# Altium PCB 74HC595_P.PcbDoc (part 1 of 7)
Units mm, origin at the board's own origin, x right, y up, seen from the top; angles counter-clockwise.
Board outline 89.11 x 89.03 mm, 2 copper layers (Top Layer, Bottom Layer); 552 components, 23 nets, 1488 pads, 408 vias.
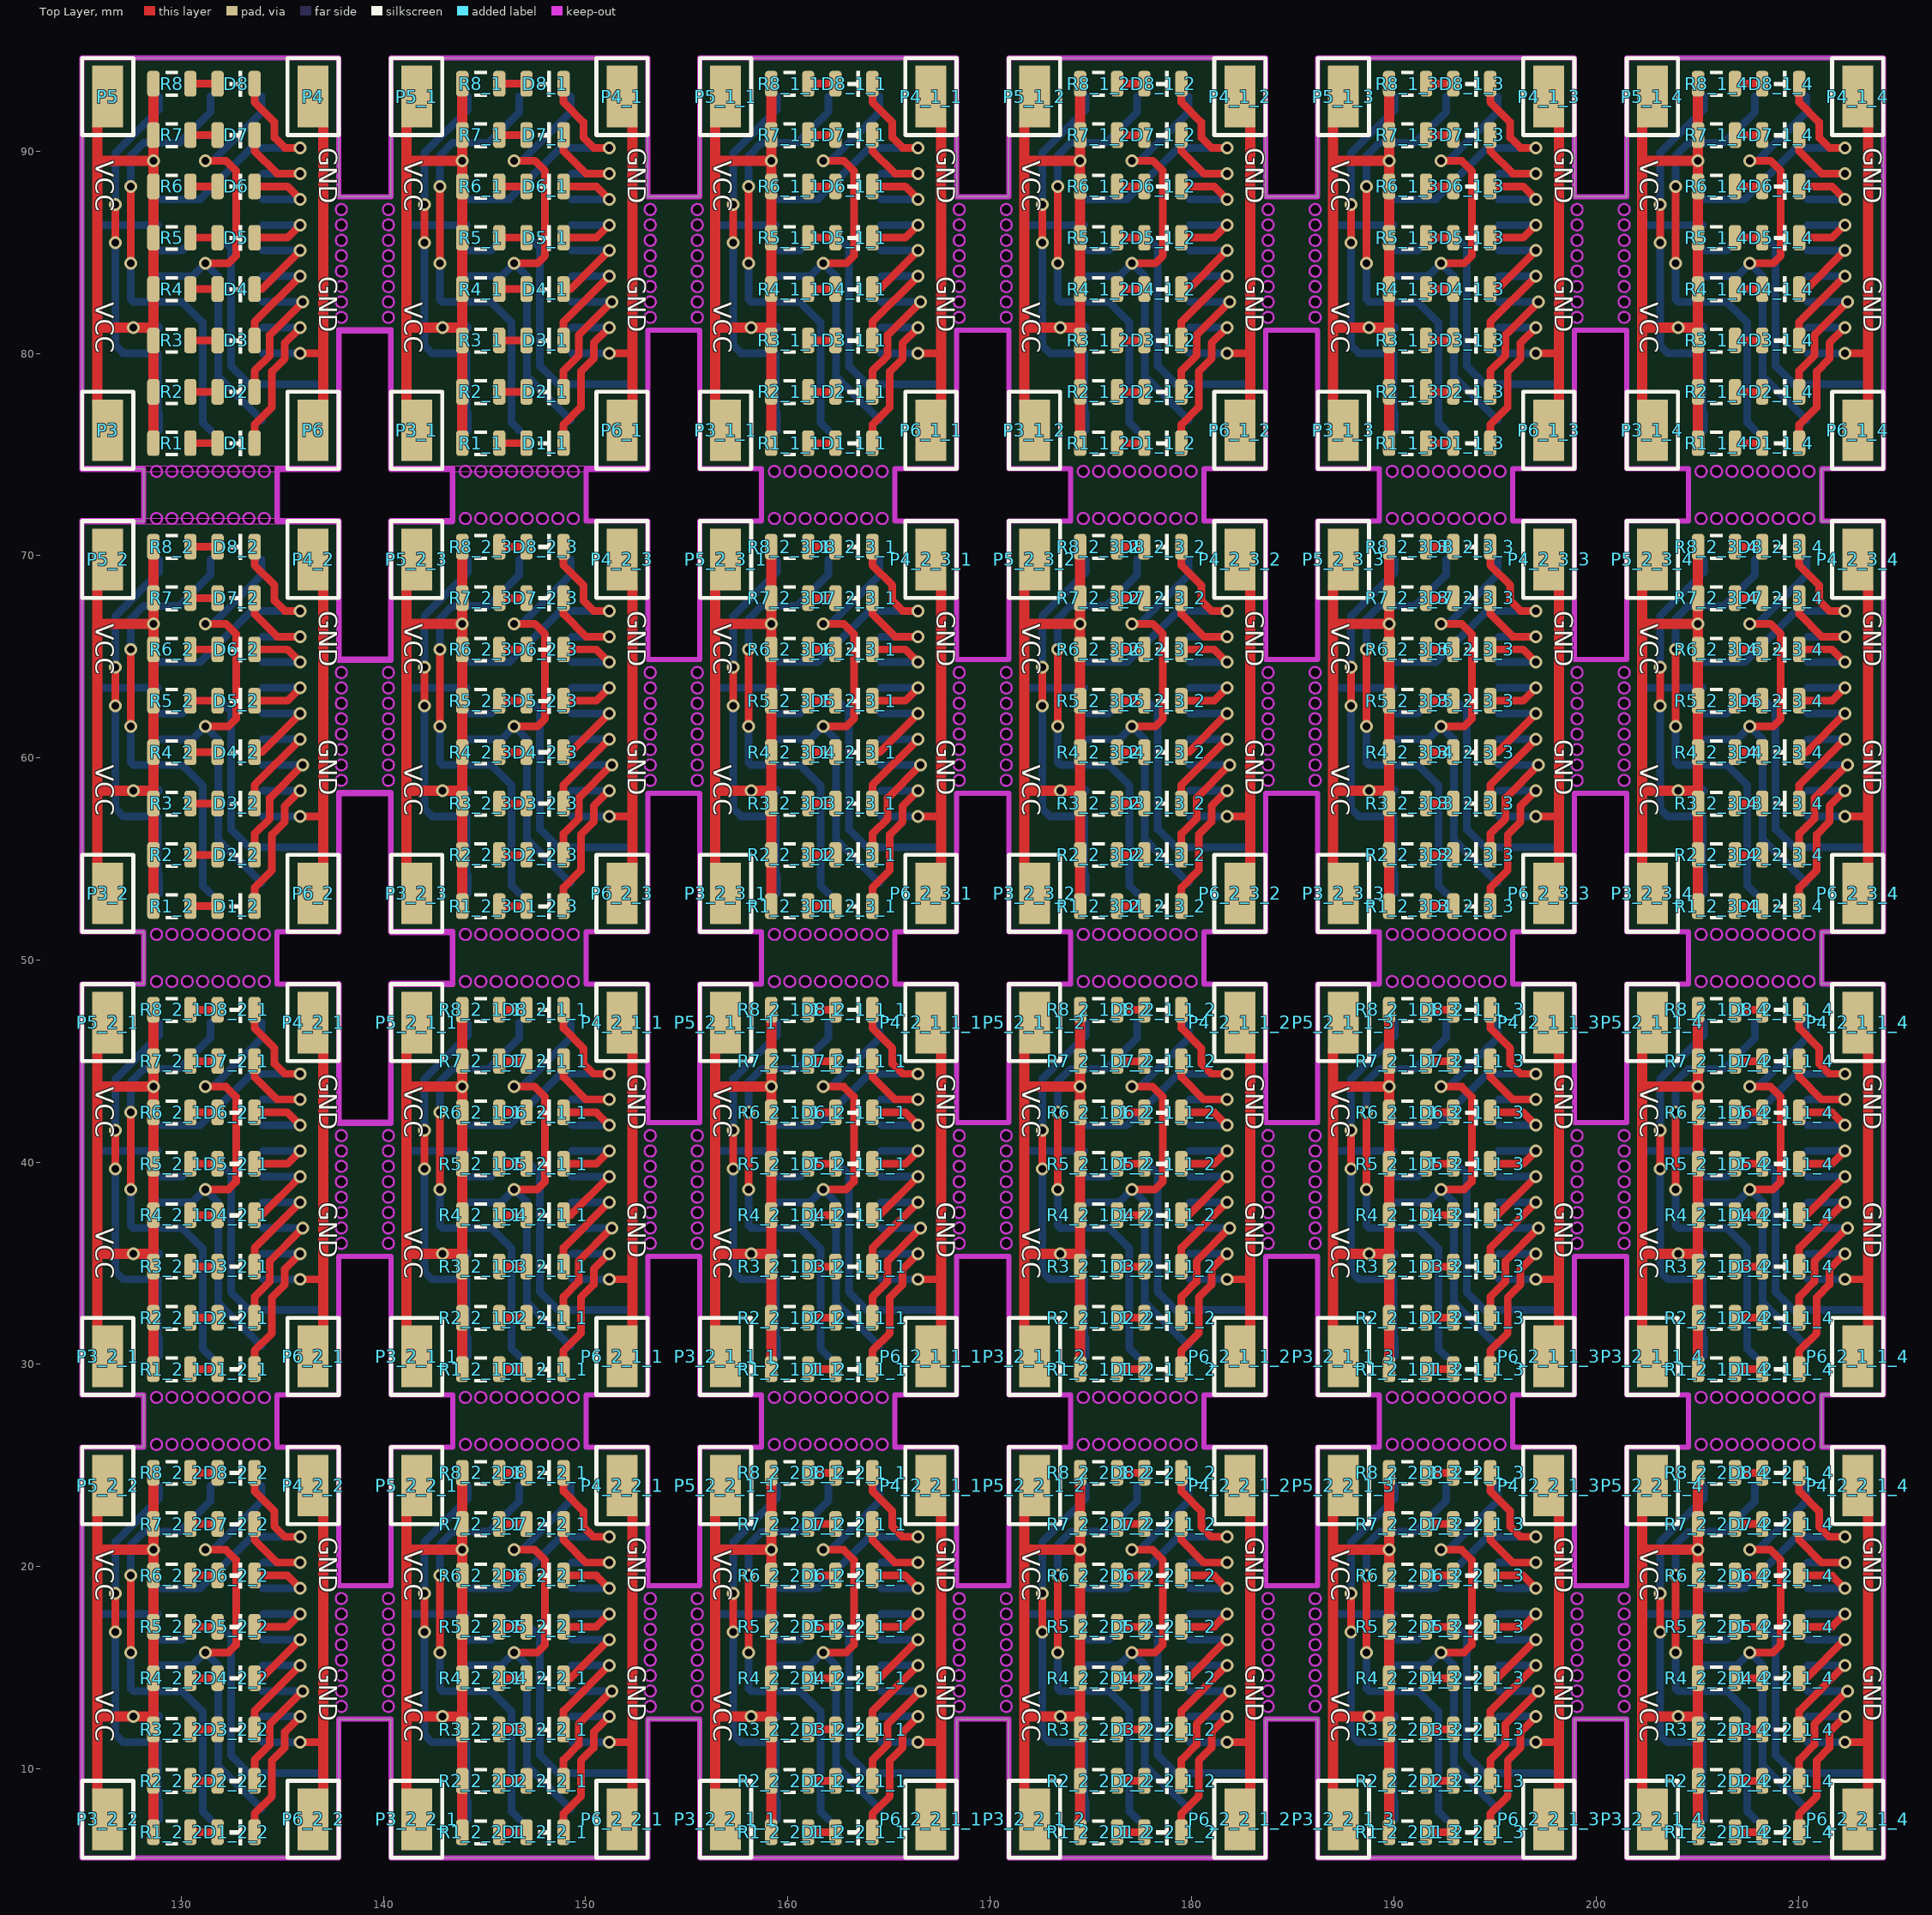
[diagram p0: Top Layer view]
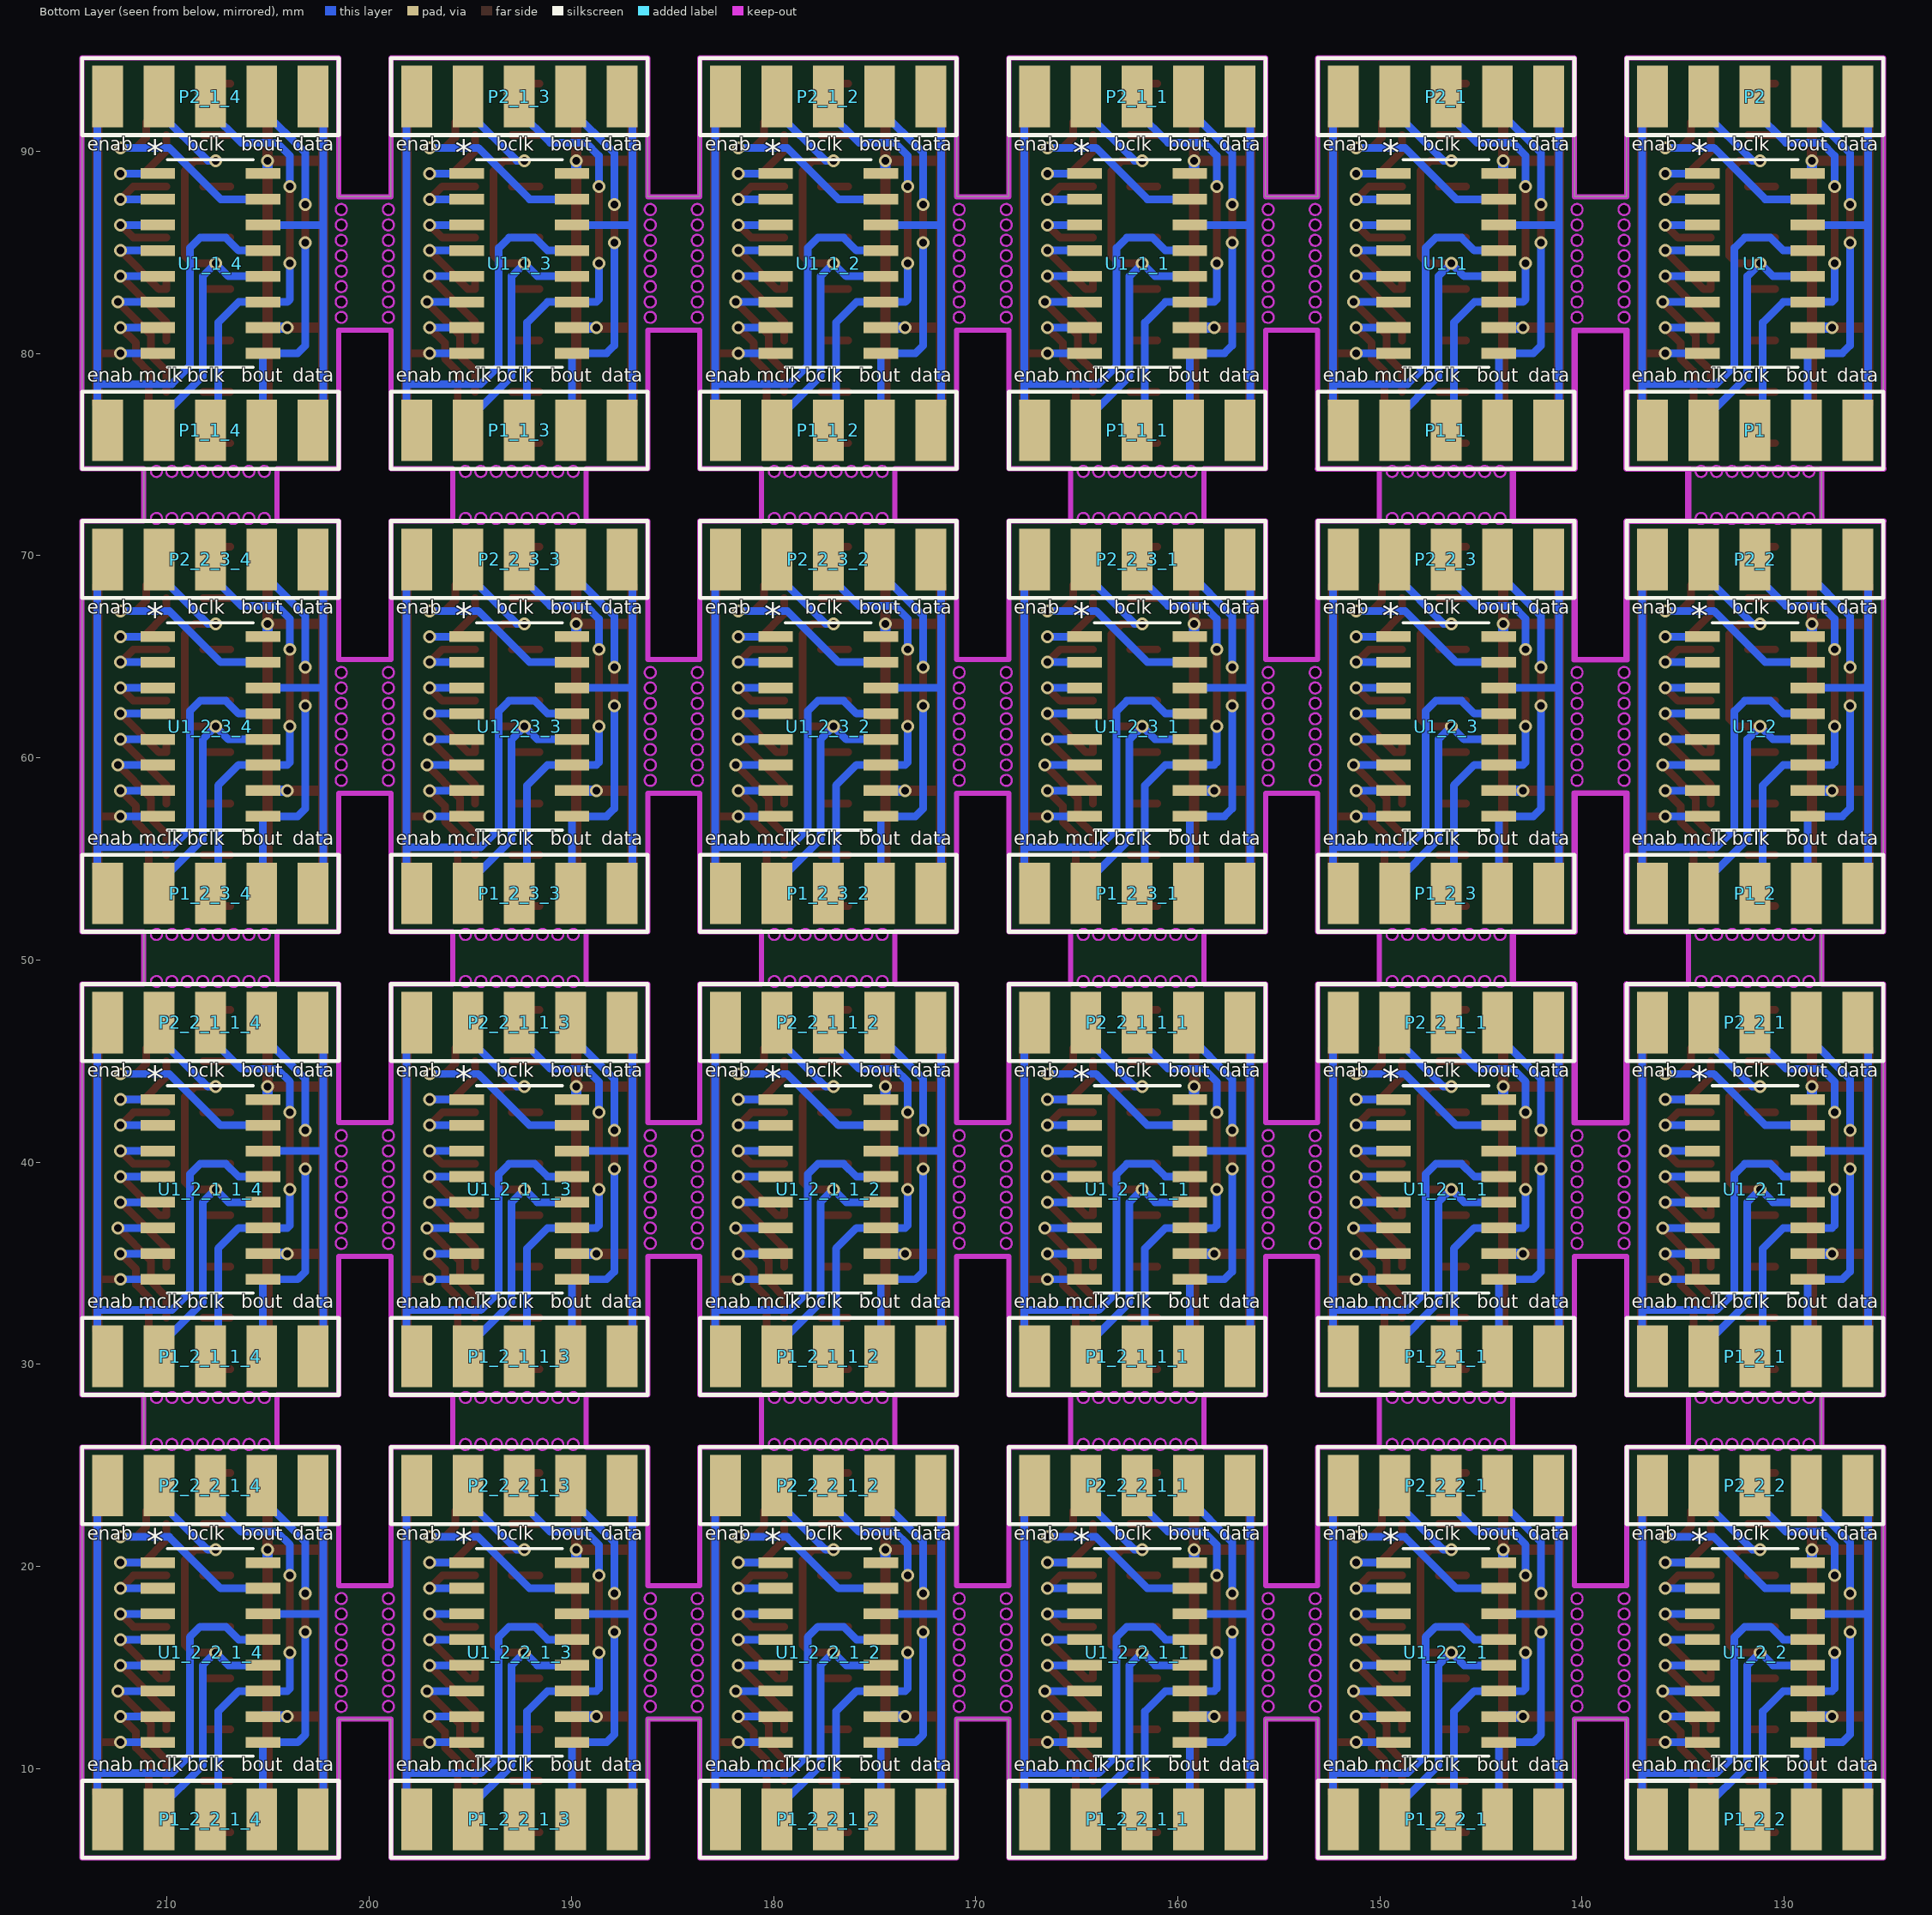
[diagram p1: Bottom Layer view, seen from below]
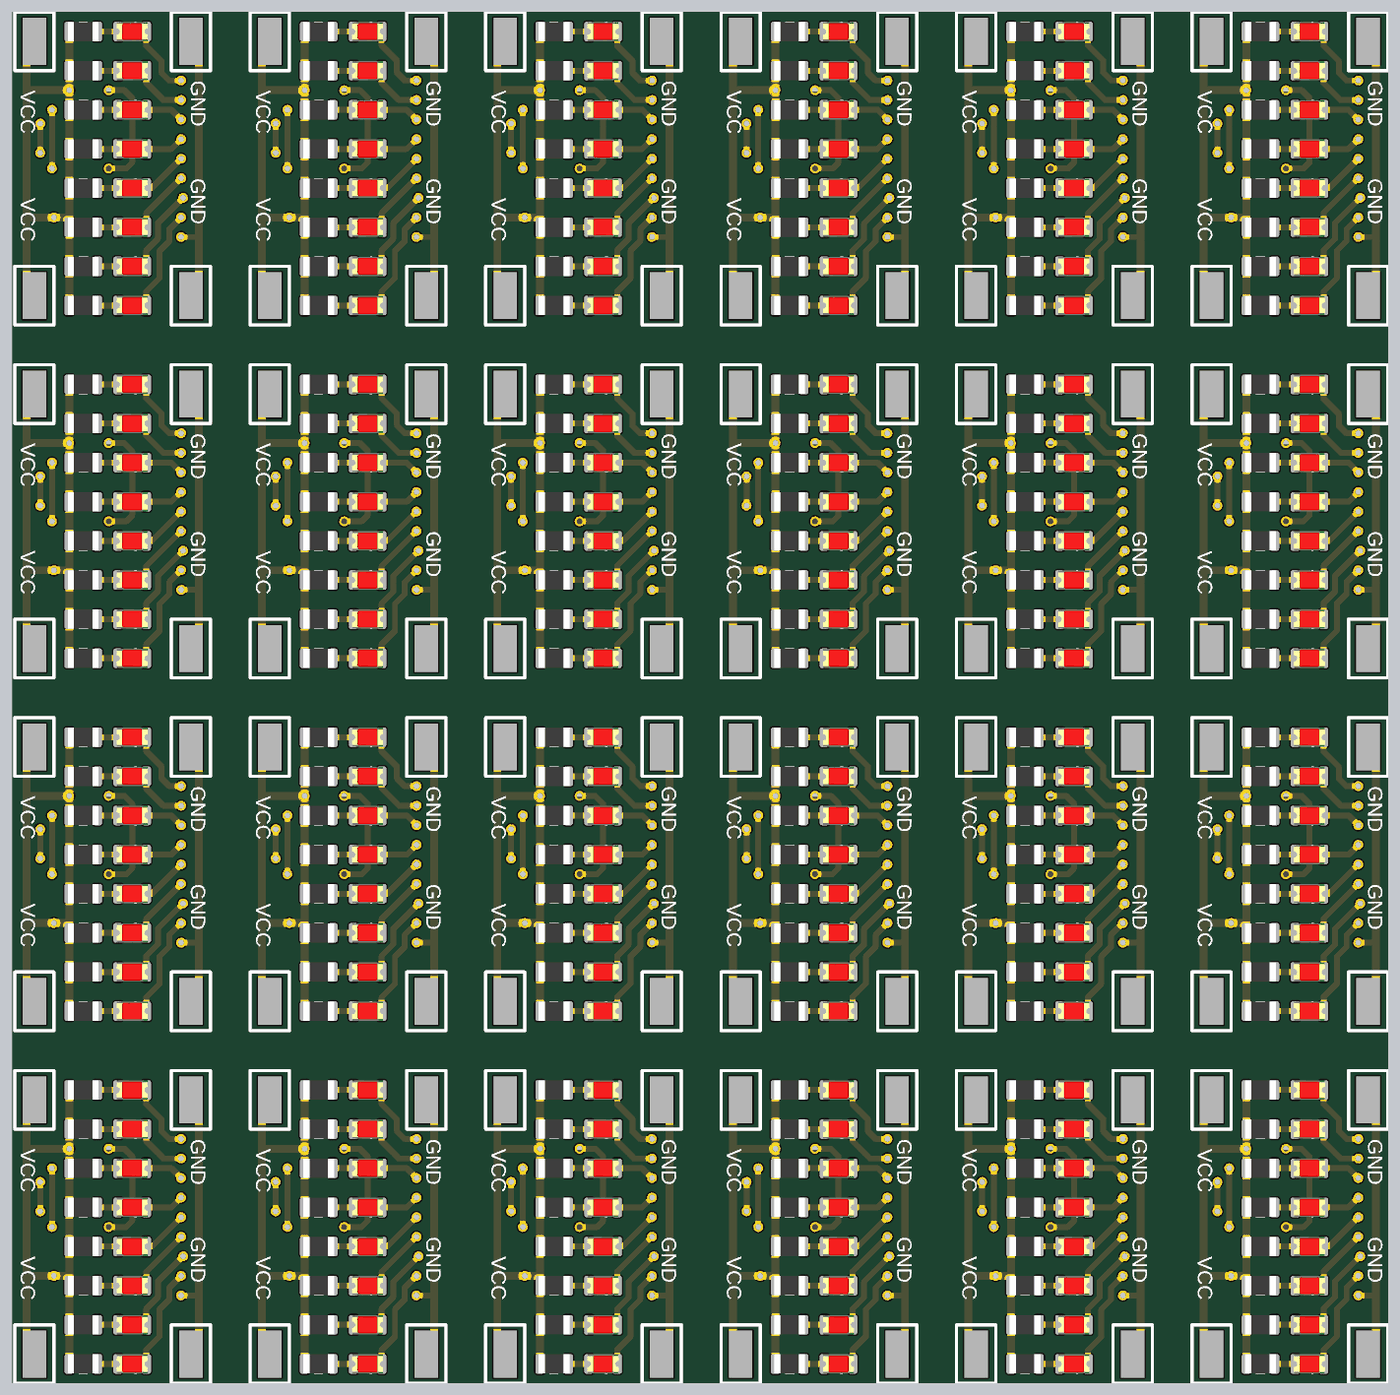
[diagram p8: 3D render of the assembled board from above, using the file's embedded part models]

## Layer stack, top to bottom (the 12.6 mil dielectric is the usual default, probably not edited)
Top Solder: solder mask 0.0102, Solder Resist, Dk 3.5
Top Layer: signal copper 0.0356
Dielectric 1: dielectric 0.32, FR-4, Dk 4.8
Bottom Layer: signal copper 0.0356
Bottom Solder: solder mask 0.0102, Solder Resist, Dk 3.5

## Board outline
125.095,25.909 128.143,25.909 128.143,28.491 125.095,28.491 125.095,48.811 128.143,48.811 128.143,51.393 125.095,51.393 125.095,71.713 128.143,71.713 128.143,74.295 125.095,74.295 125.095,94.615 137.795,94.615 137.795,87.757 140.377,87.757 140.377,94.615 153.077,94.615 153.077,87.757 155.659,87.757 155.659,94.615 168.359,94.615 168.359,87.757 170.941,87.757 170.941,94.615 183.641,94.615 183.641,87.757 186.223,87.757 186.223,94.615 198.923,94.615 198.923,87.757 201.505,87.757 201.505,94.615 214.205,94.615 214.205,74.295 211.157,74.295 211.157,71.713 214.205,71.713 214.205,51.393 211.157,51.393 211.157,48.811 214.205,48.811 214.205,28.491 211.157,28.491 211.157,25.909 214.205,25.909 214.205,5.589 201.505,5.589 201.505,12.447 198.923,12.447 198.923,5.589 186.223,5.589 186.223,12.447 183.641,12.447 183.641,5.589 170.941,5.589 170.941,12.447 168.359,12.447 168.359,5.589 155.659,5.589 155.659,12.447 153.077,12.447 153.077,5.589 140.377,5.589 140.377,12.447 137.795,12.447 137.795,5.589 125.095,5.589
cut-out: 205.188,25.761 ccw(c205.188,26.036) 205.463,26.036 ccw(c205.188,26.036) 205.188,26.311 ccw(c205.188,26.036) 204.913,26.036 ccw(c205.188,26.036)
cut-out: 205.188,28.089 ccw(c205.188,28.364) 205.463,28.364 ccw(c205.188,28.364) 205.188,28.639 ccw(c205.188,28.364) 204.913,28.364 ccw(c205.188,28.364)
cut-out: 205.95,25.761 ccw(c205.95,26.036) 206.225,26.036 ccw(c205.95,26.036) 205.95,26.311 ccw(c205.95,26.036) 205.675,26.036 ccw(c205.95,26.036)
cut-out: 206.712,28.089 cw(c206.712,28.364) 206.437,28.364 cw(c206.712,28.364) 206.712,28.639 cw(c206.712,28.364) 206.987,28.364 cw(c206.712,28.364)
cut-out: 205.95,28.089 ccw(c205.95,28.364) 206.225,28.364 ccw(c205.95,28.364) 205.95,28.639 ccw(c205.95,28.364) 205.675,28.364 ccw(c205.95,28.364)
cut-out: 207.474,28.089 ccw(c207.474,28.364) 207.749,28.364 ccw(c207.474,28.364) 207.474,28.639 ccw(c207.474,28.364) 207.199,28.364 ccw(c207.474,28.364)
cut-out: 207.474,25.761 ccw(c207.474,26.036) 207.749,26.036 ccw(c207.474,26.036) 207.474,26.311 ccw(c207.474,26.036) 207.199,26.036 ccw(c207.474,26.036)
cut-out: 206.712,25.761 ccw(c206.712,26.036) 206.987,26.036 ccw(c206.712,26.036) 206.712,26.311 ccw(c206.712,26.036) 206.437,26.036 ccw(c206.712,26.036)
cut-out: 208.236,25.761 ccw(c208.236,26.036) 208.511,26.036 ccw(c208.236,26.036) 208.236,26.311 ccw(c208.236,26.036) 207.961,26.036 ccw(c208.236,26.036)
cut-out: 208.998,25.761 ccw(c208.998,26.036) 209.273,26.036 ccw(c208.998,26.036) 208.998,26.311 ccw(c208.998,26.036) 208.723,26.036 ccw(c208.998,26.036)
cut-out: 209.76,25.761 ccw(c209.76,26.036) 210.035,26.036 ccw(c209.76,26.036) 209.76,26.311 ccw(c209.76,26.036) 209.485,26.036 ccw(c209.76,26.036)
cut-out: 210.522,25.761 ccw(c210.522,26.036) 210.797,26.036 ccw(c210.522,26.036) 210.522,26.311 ccw(c210.522,26.036) 210.247,26.036 ccw(c210.522,26.036)
cut-out: 210.522,28.089 ccw(c210.522,28.364) 210.797,28.364 ccw(c210.522,28.364) 210.522,28.639 ccw(c210.522,28.364) 210.247,28.364 ccw(c210.522,28.364)
cut-out: 209.76,28.089 ccw(c209.76,28.364) 210.035,28.364 ccw(c209.76,28.364) 209.76,28.639 ccw(c209.76,28.364) 209.485,28.364 ccw(c209.76,28.364)
cut-out: 208.998,28.089 ccw(c208.998,28.364) 209.273,28.364 ccw(c208.998,28.364) 208.998,28.639 ccw(c208.998,28.364) 208.723,28.364 ccw(c208.998,28.364)
cut-out: 208.236,28.089 ccw(c208.236,28.364) 208.511,28.364 ccw(c208.236,28.364) 208.236,28.639 ccw(c208.236,28.364) 207.961,28.364 ccw(c208.236,28.364)
cut-out: 189.906,25.761 ccw(c189.906,26.036) 190.181,26.036 ccw(c189.906,26.036) 189.906,26.311 ccw(c189.906,26.036) 189.631,26.036 ccw(c189.906,26.036)
cut-out: 189.906,28.089 ccw(c189.906,28.364) 190.181,28.364 ccw(c189.906,28.364) 189.906,28.639 ccw(c189.906,28.364) 189.631,28.364 ccw(c189.906,28.364)
cut-out: 190.668,25.761 ccw(c190.668,26.036) 190.943,26.036 ccw(c190.668,26.036) 190.668,26.311 ccw(c190.668,26.036) 190.393,26.036 ccw(c190.668,26.036)
cut-out: 191.43,28.089 cw(c191.43,28.364) 191.155,28.364 cw(c191.43,28.364) 191.43,28.639 cw(c191.43,28.364) 191.705,28.364 cw(c191.43,28.364)
cut-out: 190.668,28.089 ccw(c190.668,28.364) 190.943,28.364 ccw(c190.668,28.364) 190.668,28.639 ccw(c190.668,28.364) 190.393,28.364 ccw(c190.668,28.364)
cut-out: 192.192,28.089 ccw(c192.192,28.364) 192.467,28.364 ccw(c192.192,28.364) 192.192,28.639 ccw(c192.192,28.364) 191.917,28.364 ccw(c192.192,28.364)
cut-out: 192.192,25.761 ccw(c192.192,26.036) 192.467,26.036 ccw(c192.192,26.036) 192.192,26.311 ccw(c192.192,26.036) 191.917,26.036 ccw(c192.192,26.036)
cut-out: 191.43,25.761 ccw(c191.43,26.036) 191.705,26.036 ccw(c191.43,26.036) 191.43,26.311 ccw(c191.43,26.036) 191.155,26.036 ccw(c191.43,26.036)
cut-out: 192.954,25.761 ccw(c192.954,26.036) 193.229,26.036 ccw(c192.954,26.036) 192.954,26.311 ccw(c192.954,26.036) 192.679,26.036 ccw(c192.954,26.036)
cut-out: 193.716,25.761 ccw(c193.716,26.036) 193.991,26.036 ccw(c193.716,26.036) 193.716,26.311 ccw(c193.716,26.036) 193.441,26.036 ccw(c193.716,26.036)
cut-out: 194.478,25.761 ccw(c194.478,26.036) 194.753,26.036 ccw(c194.478,26.036) 194.478,26.311 ccw(c194.478,26.036) 194.203,26.036 ccw(c194.478,26.036)
cut-out: 195.24,25.761 ccw(c195.24,26.036) 195.515,26.036 ccw(c195.24,26.036) 195.24,26.311 ccw(c195.24,26.036) 194.965,26.036 ccw(c195.24,26.036)
cut-out: 195.24,28.089 ccw(c195.24,28.364) 195.515,28.364 ccw(c195.24,28.364) 195.24,28.639 ccw(c195.24,28.364) 194.965,28.364 ccw(c195.24,28.364)
cut-out: 194.478,28.089 ccw(c194.478,28.364) 194.753,28.364 ccw(c194.478,28.364) 194.478,28.639 ccw(c194.478,28.364) 194.203,28.364 ccw(c194.478,28.364)
cut-out: 193.716,28.089 ccw(c193.716,28.364) 193.991,28.364 ccw(c193.716,28.364) 193.716,28.639 ccw(c193.716,28.364) 193.441,28.364 ccw(c193.716,28.364)
cut-out: 192.954,28.089 ccw(c192.954,28.364) 193.229,28.364 ccw(c192.954,28.364) 192.954,28.639 ccw(c192.954,28.364) 192.679,28.364 ccw(c192.954,28.364)
cut-out: 174.624,25.761 ccw(c174.624,26.036) 174.899,26.036 ccw(c174.624,26.036) 174.624,26.311 ccw(c174.624,26.036) 174.349,26.036 ccw(c174.624,26.036)
cut-out: 174.624,28.089 ccw(c174.624,28.364) 174.899,28.364 ccw(c174.624,28.364) 174.624,28.639 ccw(c174.624,28.364) 174.349,28.364 ccw(c174.624,28.364)
cut-out: 175.386,25.761 ccw(c175.386,26.036) 175.661,26.036 ccw(c175.386,26.036) 175.386,26.311 ccw(c175.386,26.036) 175.111,26.036 ccw(c175.386,26.036)
cut-out: 176.148,28.089 cw(c176.148,28.364) 175.873,28.364 cw(c176.148,28.364) 176.148,28.639 cw(c176.148,28.364) 176.423,28.364 cw(c176.148,28.364)
cut-out: 175.386,28.089 ccw(c175.386,28.364) 175.661,28.364 ccw(c175.386,28.364) 175.386,28.639 ccw(c175.386,28.364) 175.111,28.364 ccw(c175.386,28.364)
cut-out: 176.91,28.089 ccw(c176.91,28.364) 177.185,28.364 ccw(c176.91,28.364) 176.91,28.639 ccw(c176.91,28.364) 176.635,28.364 ccw(c176.91,28.364)
cut-out: 176.91,25.761 ccw(c176.91,26.036) 177.185,26.036 ccw(c176.91,26.036) 176.91,26.311 ccw(c176.91,26.036) 176.635,26.036 ccw(c176.91,26.036)
cut-out: 176.148,25.761 ccw(c176.148,26.036) 176.423,26.036 ccw(c176.148,26.036) 176.148,26.311 ccw(c176.148,26.036) 175.873,26.036 ccw(c176.148,26.036)
cut-out: 177.672,25.761 ccw(c177.672,26.036) 177.947,26.036 ccw(c177.672,26.036) 177.672,26.311 ccw(c177.672,26.036) 177.397,26.036 ccw(c177.672,26.036)
cut-out: 178.434,25.761 ccw(c178.434,26.036) 178.709,26.036 ccw(c178.434,26.036) 178.434,26.311 ccw(c178.434,26.036) 178.159,26.036 ccw(c178.434,26.036)
cut-out: 179.196,25.761 ccw(c179.196,26.036) 179.471,26.036 ccw(c179.196,26.036) 179.196,26.311 ccw(c179.196,26.036) 178.921,26.036 ccw(c179.196,26.036)
cut-out: 179.958,25.761 ccw(c179.958,26.036) 180.233,26.036 ccw(c179.958,26.036) 179.958,26.311 ccw(c179.958,26.036) 179.683,26.036 ccw(c179.958,26.036)
cut-out: 179.958,28.089 ccw(c179.958,28.364) 180.233,28.364 ccw(c179.958,28.364) 179.958,28.639 ccw(c179.958,28.364) 179.683,28.364 ccw(c179.958,28.364)
cut-out: 179.196,28.089 ccw(c179.196,28.364) 179.471,28.364 ccw(c179.196,28.364) 179.196,28.639 ccw(c179.196,28.364) 178.921,28.364 ccw(c179.196,28.364)
cut-out: 178.434,28.089 ccw(c178.434,28.364) 178.709,28.364 ccw(c178.434,28.364) 178.434,28.639 ccw(c178.434,28.364) 178.159,28.364 ccw(c178.434,28.364)
cut-out: 177.672,28.089 ccw(c177.672,28.364) 177.947,28.364 ccw(c177.672,28.364) 177.672,28.639 ccw(c177.672,28.364) 177.397,28.364 ccw(c177.672,28.364)
cut-out: 159.342,25.761 ccw(c159.342,26.036) 159.617,26.036 ccw(c159.342,26.036) 159.342,26.311 ccw(c159.342,26.036) 159.067,26.036 ccw(c159.342,26.036)
cut-out: 159.342,28.089 ccw(c159.342,28.364) 159.617,28.364 ccw(c159.342,28.364) 159.342,28.639 ccw(c159.342,28.364) 159.067,28.364 ccw(c159.342,28.364)
cut-out: 160.104,25.761 ccw(c160.104,26.036) 160.379,26.036 ccw(c160.104,26.036) 160.104,26.311 ccw(c160.104,26.036) 159.829,26.036 ccw(c160.104,26.036)
cut-out: 160.866,28.089 cw(c160.866,28.364) 160.591,28.364 cw(c160.866,28.364) 160.866,28.639 cw(c160.866,28.364) 161.141,28.364 cw(c160.866,28.364)
cut-out: 160.104,28.089 ccw(c160.104,28.364) 160.379,28.364 ccw(c160.104,28.364) 160.104,28.639 ccw(c160.104,28.364) 159.829,28.364 ccw(c160.104,28.364)
cut-out: 161.628,28.089 ccw(c161.628,28.364) 161.903,28.364 ccw(c161.628,28.364) 161.628,28.639 ccw(c161.628,28.364) 161.353,28.364 ccw(c161.628,28.364)
cut-out: 161.628,25.761 ccw(c161.628,26.036) 161.903,26.036 ccw(c161.628,26.036) 161.628,26.311 ccw(c161.628,26.036) 161.353,26.036 ccw(c161.628,26.036)
cut-out: 160.866,25.761 ccw(c160.866,26.036) 161.141,26.036 ccw(c160.866,26.036) 160.866,26.311 ccw(c160.866,26.036) 160.591,26.036 ccw(c160.866,26.036)
cut-out: 162.39,25.761 ccw(c162.39,26.036) 162.665,26.036 ccw(c162.39,26.036) 162.39,26.311 ccw(c162.39,26.036) 162.115,26.036 ccw(c162.39,26.036)
cut-out: 163.152,25.761 ccw(c163.152,26.036) 163.427,26.036 ccw(c163.152,26.036) 163.152,26.311 ccw(c163.152,26.036) 162.877,26.036 ccw(c163.152,26.036)
cut-out: 163.914,25.761 ccw(c163.914,26.036) 164.189,26.036 ccw(c163.914,26.036) 163.914,26.311 ccw(c163.914,26.036) 163.639,26.036 ccw(c163.914,26.036)
cut-out: 164.676,25.761 ccw(c164.676,26.036) 164.951,26.036 ccw(c164.676,26.036) 164.676,26.311 ccw(c164.676,26.036) 164.401,26.036 ccw(c164.676,26.036)
cut-out: 164.676,28.089 ccw(c164.676,28.364) 164.951,28.364 ccw(c164.676,28.364) 164.676,28.639 ccw(c164.676,28.364) 164.401,28.364 ccw(c164.676,28.364)
cut-out: 163.914,28.089 ccw(c163.914,28.364) 164.189,28.364 ccw(c163.914,28.364) 163.914,28.639 ccw(c163.914,28.364) 163.639,28.364 ccw(c163.914,28.364)
cut-out: 163.152,28.089 ccw(c163.152,28.364) 163.427,28.364 ccw(c163.152,28.364) 163.152,28.639 ccw(c163.152,28.364) 162.877,28.364 ccw(c163.152,28.364)
cut-out: 162.39,28.089 ccw(c162.39,28.364) 162.665,28.364 ccw(c162.39,28.364) 162.39,28.639 ccw(c162.39,28.364) 162.115,28.364 ccw(c162.39,28.364)
cut-out: 144.06,25.761 ccw(c144.06,26.036) 144.335,26.036 ccw(c144.06,26.036) 144.06,26.311 ccw(c144.06,26.036) 143.785,26.036 ccw(c144.06,26.036)
cut-out: 144.06,28.089 ccw(c144.06,28.364) 144.335,28.364 ccw(c144.06,28.364) 144.06,28.639 ccw(c144.06,28.364) 143.785,28.364 ccw(c144.06,28.364)
cut-out: 144.822,25.761 ccw(c144.822,26.036) 145.097,26.036 ccw(c144.822,26.036) 144.822,26.311 ccw(c144.822,26.036) 144.547,26.036 ccw(c144.822,26.036)
cut-out: 145.584,28.089 cw(c145.584,28.364) 145.309,28.364 cw(c145.584,28.364) 145.584,28.639 cw(c145.584,28.364) 145.859,28.364 cw(c145.584,28.364)
cut-out: 144.822,28.089 ccw(c144.822,28.364) 145.097,28.364 ccw(c144.822,28.364) 144.822,28.639 ccw(c144.822,28.364) 144.547,28.364 ccw(c144.822,28.364)
cut-out: 146.346,28.089 ccw(c146.346,28.364) 146.621,28.364 ccw(c146.346,28.364) 146.346,28.639 ccw(c146.346,28.364) 146.071,28.364 ccw(c146.346,28.364)
cut-out: 146.346,25.761 ccw(c146.346,26.036) 146.621,26.036 ccw(c146.346,26.036) 146.346,26.311 ccw(c146.346,26.036) 146.071,26.036 ccw(c146.346,26.036)
cut-out: 145.584,25.761 ccw(c145.584,26.036) 145.859,26.036 ccw(c145.584,26.036) 145.584,26.311 ccw(c145.584,26.036) 145.309,26.036 ccw(c145.584,26.036)
cut-out: 147.108,25.761 ccw(c147.108,26.036) 147.383,26.036 ccw(c147.108,26.036) 147.108,26.311 ccw(c147.108,26.036) 146.833,26.036 ccw(c147.108,26.036)
cut-out: 147.87,25.761 ccw(c147.87,26.036) 148.145,26.036 ccw(c147.87,26.036) 147.87,26.311 ccw(c147.87,26.036) 147.595,26.036 ccw(c147.87,26.036)
cut-out: 148.632,25.761 ccw(c148.632,26.036) 148.907,26.036 ccw(c148.632,26.036) 148.632,26.311 ccw(c148.632,26.036) 148.357,26.036 ccw(c148.632,26.036)
cut-out: 149.394,25.761 ccw(c149.394,26.036) 149.669,26.036 ccw(c149.394,26.036) 149.394,26.311 ccw(c149.394,26.036) 149.119,26.036 ccw(c149.394,26.036)
cut-out: 149.394,28.089 ccw(c149.394,28.364) 149.669,28.364 ccw(c149.394,28.364) 149.394,28.639 ccw(c149.394,28.364) 149.119,28.364 ccw(c149.394,28.364)
cut-out: 148.632,28.089 ccw(c148.632,28.364) 148.907,28.364 ccw(c148.632,28.364) 148.632,28.639 ccw(c148.632,28.364) 148.357,28.364 ccw(c148.632,28.364)
cut-out: 147.87,28.089 ccw(c147.87,28.364) 148.145,28.364 ccw(c147.87,28.364) 147.87,28.639 ccw(c147.87,28.364) 147.595,28.364 ccw(c147.87,28.364)
cut-out: 147.108,28.089 ccw(c147.108,28.364) 147.383,28.364 ccw(c147.108,28.364) 147.108,28.639 ccw(c147.108,28.364) 146.833,28.364 ccw(c147.108,28.364)
cut-out: 128.778,25.761 ccw(c128.778,26.036) 129.053,26.036 ccw(c128.778,26.036) 128.778,26.311 ccw(c128.778,26.036) 128.503,26.036 ccw(c128.778,26.036)
cut-out: 128.778,28.089 ccw(c128.778,28.364) 129.053,28.364 ccw(c128.778,28.364) 128.778,28.639 ccw(c128.778,28.364) 128.503,28.364 ccw(c128.778,28.364)
cut-out: 129.54,25.761 ccw(c129.54,26.036) 129.815,26.036 ccw(c129.54,26.036) 129.54,26.311 ccw(c129.54,26.036) 129.265,26.036 ccw(c129.54,26.036)
cut-out: 130.302,28.089 cw(c130.302,28.364) 130.027,28.364 cw(c130.302,28.364) 130.302,28.639 cw(c130.302,28.364) 130.577,28.364 cw(c130.302,28.364)
cut-out: 129.54,28.089 ccw(c129.54,28.364) 129.815,28.364 ccw(c129.54,28.364) 129.54,28.639 ccw(c129.54,28.364) 129.265,28.364 ccw(c129.54,28.364)
cut-out: 131.064,28.089 ccw(c131.064,28.364) 131.339,28.364 ccw(c131.064,28.364) 131.064,28.639 ccw(c131.064,28.364) 130.789,28.364 ccw(c131.064,28.364)
cut-out: 131.064,25.761 ccw(c131.064,26.036) 131.339,26.036 ccw(c131.064,26.036) 131.064,26.311 ccw(c131.064,26.036) 130.789,26.036 ccw(c131.064,26.036)
cut-out: 130.302,25.761 ccw(c130.302,26.036) 130.577,26.036 ccw(c130.302,26.036) 130.302,26.311 ccw(c130.302,26.036) 130.027,26.036 ccw(c130.302,26.036)
cut-out: 131.826,25.761 ccw(c131.826,26.036) 132.101,26.036 ccw(c131.826,26.036) 131.826,26.311 ccw(c131.826,26.036) 131.551,26.036 ccw(c131.826,26.036)
cut-out: 132.588,25.761 ccw(c132.588,26.036) 132.863,26.036 ccw(c132.588,26.036) 132.588,26.311 ccw(c132.588,26.036) 132.313,26.036 ccw(c132.588,26.036)
cut-out: 133.35,25.761 ccw(c133.35,26.036) 133.625,26.036 ccw(c133.35,26.036) 133.35,26.311 ccw(c133.35,26.036) 133.075,26.036 ccw(c133.35,26.036)
cut-out: 134.112,25.761 ccw(c134.112,26.036) 134.387,26.036 ccw(c134.112,26.036) 134.112,26.311 ccw(c134.112,26.036) 133.837,26.036 ccw(c134.112,26.036)
cut-out: 134.112,28.089 ccw(c134.112,28.364) 134.387,28.364 ccw(c134.112,28.364) 134.112,28.639 ccw(c134.112,28.364) 133.837,28.364 ccw(c134.112,28.364)
cut-out: 133.35,28.089 ccw(c133.35,28.364) 133.625,28.364 ccw(c133.35,28.364) 133.35,28.639 ccw(c133.35,28.364) 133.075,28.364 ccw(c133.35,28.364)
cut-out: 132.588,28.089 ccw(c132.588,28.364) 132.863,28.364 ccw(c132.588,28.364) 132.588,28.639 ccw(c132.588,28.364) 132.313,28.364 ccw(c132.588,28.364)
cut-out: 131.826,28.089 ccw(c131.826,28.364) 132.101,28.364 ccw(c131.826,28.364) 131.826,28.639 ccw(c131.826,28.364) 131.551,28.364 ccw(c131.826,28.364)
cut-out: 205.188,48.663 ccw(c205.188,48.938) 205.463,48.938 ccw(c205.188,48.938) 205.188,49.213 ccw(c205.188,48.938) 204.913,48.938 ccw(c205.188,48.938)
cut-out: 205.188,50.991 ccw(c205.188,51.266) 205.463,51.266 ccw(c205.188,51.266) 205.188,51.541 ccw(c205.188,51.266) 204.913,51.266 ccw(c205.188,51.266)
cut-out: 205.95,48.663 ccw(c205.95,48.938) 206.225,48.938 ccw(c205.95,48.938) 205.95,49.213 ccw(c205.95,48.938) 205.675,48.938 ccw(c205.95,48.938)
cut-out: 206.712,50.991 cw(c206.712,51.266) 206.437,51.266 cw(c206.712,51.266) 206.712,51.541 cw(c206.712,51.266) 206.987,51.266 cw(c206.712,51.266)
cut-out: 205.95,50.991 ccw(c205.95,51.266) 206.225,51.266 ccw(c205.95,51.266) 205.95,51.541 ccw(c205.95,51.266) 205.675,51.266 ccw(c205.95,51.266)
cut-out: 207.474,50.991 ccw(c207.474,51.266) 207.749,51.266 ccw(c207.474,51.266) 207.474,51.541 ccw(c207.474,51.266) 207.199,51.266 ccw(c207.474,51.266)
cut-out: 207.474,48.663 ccw(c207.474,48.938) 207.749,48.938 ccw(c207.474,48.938) 207.474,49.213 ccw(c207.474,48.938) 207.199,48.938 ccw(c207.474,48.938)
cut-out: 206.712,48.663 ccw(c206.712,48.938) 206.987,48.938 ccw(c206.712,48.938) 206.712,49.213 ccw(c206.712,48.938) 206.437,48.938 ccw(c206.712,48.938)
cut-out: 208.236,48.663 ccw(c208.236,48.938) 208.511,48.938 ccw(c208.236,48.938) 208.236,49.213 ccw(c208.236,48.938) 207.961,48.938 ccw(c208.236,48.938)
cut-out: 208.998,48.663 ccw(c208.998,48.938) 209.273,48.938 ccw(c208.998,48.938) 208.998,49.213 ccw(c208.998,48.938) 208.723,48.938 ccw(c208.998,48.938)
cut-out: 209.76,48.663 ccw(c209.76,48.938) 210.035,48.938 ccw(c209.76,48.938) 209.76,49.213 ccw(c209.76,48.938) 209.485,48.938 ccw(c209.76,48.938)
cut-out: 210.522,48.663 ccw(c210.522,48.938) 210.797,48.938 ccw(c210.522,48.938) 210.522,49.213 ccw(c210.522,48.938) 210.247,48.938 ccw(c210.522,48.938)
cut-out: 210.522,50.991 ccw(c210.522,51.266) 210.797,51.266 ccw(c210.522,51.266) 210.522,51.541 ccw(c210.522,51.266) 210.247,51.266 ccw(c210.522,51.266)
cut-out: 209.76,50.991 ccw(c209.76,51.266) 210.035,51.266 ccw(c209.76,51.266) 209.76,51.541 ccw(c209.76,51.266) 209.485,51.266 ccw(c209.76,51.266)
cut-out: 208.998,50.991 ccw(c208.998,51.266) 209.273,51.266 ccw(c208.998,51.266) 208.998,51.541 ccw(c208.998,51.266) 208.723,51.266 ccw(c208.998,51.266)
cut-out: 208.236,50.991 ccw(c208.236,51.266) 208.511,51.266 ccw(c208.236,51.266) 208.236,51.541 ccw(c208.236,51.266) 207.961,51.266 ccw(c208.236,51.266)
cut-out: 189.906,48.663 ccw(c189.906,48.938) 190.181,48.938 ccw(c189.906,48.938) 189.906,49.213 ccw(c189.906,48.938) 189.631,48.938 ccw(c189.906,48.938)
cut-out: 189.906,50.991 ccw(c189.906,51.266) 190.181,51.266 ccw(c189.906,51.266) 189.906,51.541 ccw(c189.906,51.266) 189.631,51.266 ccw(c189.906,51.266)
cut-out: 190.668,48.663 ccw(c190.668,48.938) 190.943,48.938 ccw(c190.668,48.938) 190.668,49.213 ccw(c190.668,48.938) 190.393,48.938 ccw(c190.668,48.938)
cut-out: 191.43,50.991 cw(c191.43,51.266) 191.155,51.266 cw(c191.43,51.266) 191.43,51.541 cw(c191.43,51.266) 191.705,51.266 cw(c191.43,51.266)
cut-out: 190.668,50.991 ccw(c190.668,51.266) 190.943,51.266 ccw(c190.668,51.266) 190.668,51.541 ccw(c190.668,51.266) 190.393,51.266 ccw(c190.668,51.266)
cut-out: 192.192,50.991 ccw(c192.192,51.266) 192.467,51.266 ccw(c192.192,51.266) 192.192,51.541 ccw(c192.192,51.266) 191.917,51.266 ccw(c192.192,51.266)
cut-out: 192.192,48.663 ccw(c192.192,48.938) 192.467,48.938 ccw(c192.192,48.938) 192.192,49.213 ccw(c192.192,48.938) 191.917,48.938 ccw(c192.192,48.938)
cut-out: 191.43,48.663 ccw(c191.43,48.938) 191.705,48.938 ccw(c191.43,48.938) 191.43,49.213 ccw(c191.43,48.938) 191.155,48.938 ccw(c191.43,48.938)
cut-out: 192.954,48.663 ccw(c192.954,48.938) 193.229,48.938 ccw(c192.954,48.938) 192.954,49.213 ccw(c192.954,48.938) 192.679,48.938 ccw(c192.954,48.938)
cut-out: 193.716,48.663 ccw(c193.716,48.938) 193.991,48.938 ccw(c193.716,48.938) 193.716,49.213 ccw(c193.716,48.938) 193.441,48.938 ccw(c193.716,48.938)
cut-out: 194.478,48.663 ccw(c194.478,48.938) 194.753,48.938 ccw(c194.478,48.938) 194.478,49.213 ccw(c194.478,48.938) 194.203,48.938 ccw(c194.478,48.938)
cut-out: 195.24,48.663 ccw(c195.24,48.938) 195.515,48.938 ccw(c195.24,48.938) 195.24,49.213 ccw(c195.24,48.938) 194.965,48.938 ccw(c195.24,48.938)
cut-out: 195.24,50.991 ccw(c195.24,51.266) 195.515,51.266 ccw(c195.24,51.266) 195.24,51.541 ccw(c195.24,51.266) 194.965,51.266 ccw(c195.24,51.266)
cut-out: 194.478,50.991 ccw(c194.478,51.266) 194.753,51.266 ccw(c194.478,51.266) 194.478,51.541 ccw(c194.478,51.266) 194.203,51.266 ccw(c194.478,51.266)
cut-out: 193.716,50.991 ccw(c193.716,51.266) 193.991,51.266 ccw(c193.716,51.266) 193.716,51.541 ccw(c193.716,51.266) 193.441,51.266 ccw(c193.716,51.266)
cut-out: 192.954,50.991 ccw(c192.954,51.266) 193.229,51.266 ccw(c192.954,51.266) 192.954,51.541 ccw(c192.954,51.266) 192.679,51.266 ccw(c192.954,51.266)
cut-out: 174.624,48.663 ccw(c174.624,48.938) 174.899,48.938 ccw(c174.624,48.938) 174.624,49.213 ccw(c174.624,48.938) 174.349,48.938 ccw(c174.624,48.938)
cut-out: 174.624,50.991 ccw(c174.624,51.266) 174.899,51.266 ccw(c174.624,51.266) 174.624,51.541 ccw(c174.624,51.266) 174.349,51.266 ccw(c174.624,51.266)
cut-out: 175.386,48.663 ccw(c175.386,48.938) 175.661,48.938 ccw(c175.386,48.938) 175.386,49.213 ccw(c175.386,48.938) 175.111,48.938 ccw(c175.386,48.938)
cut-out: 176.148,50.991 cw(c176.148,51.266) 175.873,51.266 cw(c176.148,51.266) 176.148,51.541 cw(c176.148,51.266) 176.423,51.266 cw(c176.148,51.266)
cut-out: 175.386,50.991 ccw(c175.386,51.266) 175.661,51.266 ccw(c175.386,51.266) 175.386,51.541 ccw(c175.386,51.266) 175.111,51.266 ccw(c175.386,51.266)
cut-out: 176.91,50.991 ccw(c176.91,51.266) 177.185,51.266 ccw(c176.91,51.266) 176.91,51.541 ccw(c176.91,51.266) 176.635,51.266 ccw(c176.91,51.266)
cut-out: 176.91,48.663 ccw(c176.91,48.938) 177.185,48.938 ccw(c176.91,48.938) 176.91,49.213 ccw(c176.91,48.938) 176.635,48.938 ccw(c176.91,48.938)
cut-out: 176.148,48.663 ccw(c176.148,48.938) 176.423,48.938 ccw(c176.148,48.938) 176.148,49.213 ccw(c176.148,48.938) 175.873,48.938 ccw(c176.148,48.938)
cut-out: 177.672,48.663 ccw(c177.672,48.938) 177.947,48.938 ccw(c177.672,48.938) 177.672,49.213 ccw(c177.672,48.938) 177.397,48.938 ccw(c177.672,48.938)
cut-out: 178.434,48.663 ccw(c178.434,48.938) 178.709,48.938 ccw(c178.434,48.938) 178.434,49.213 ccw(c178.434,48.938) 178.159,48.938 ccw(c178.434,48.938)
cut-out: 179.196,48.663 ccw(c179.196,48.938) 179.471,48.938 ccw(c179.196,48.938) 179.196,49.213 ccw(c179.196,48.938) 178.921,48.938 ccw(c179.196,48.938)
cut-out: 179.958,48.663 ccw(c179.958,48.938) 180.233,48.938 ccw(c179.958,48.938) 179.958,49.213 ccw(c179.958,48.938) 179.683,48.938 ccw(c179.958,48.938)
cut-out: 179.958,50.991 ccw(c179.958,51.266) 180.233,51.266 ccw(c179.958,51.266) 179.958,51.541 ccw(c179.958,51.266) 179.683,51.266 ccw(c179.958,51.266)
cut-out: 179.196,50.991 ccw(c179.196,51.266) 179.471,51.266 ccw(c179.196,51.266) 179.196,51.541 ccw(c179.196,51.266) 178.921,51.266 ccw(c179.196,51.266)
cut-out: 178.434,50.991 ccw(c178.434,51.266) 178.709,51.266 ccw(c178.434,51.266) 178.434,51.541 ccw(c178.434,51.266) 178.159,51.266 ccw(c178.434,51.266)
cut-out: 177.672,50.991 ccw(c177.672,51.266) 177.947,51.266 ccw(c177.672,51.266) 177.672,51.541 ccw(c177.672,51.266) 177.397,51.266 ccw(c177.672,51.266)
cut-out: 159.342,48.663 ccw(c159.342,48.938) 159.617,48.938 ccw(c159.342,48.938) 159.342,49.213 ccw(c159.342,48.938) 159.067,48.938 ccw(c159.342,48.938)
cut-out: 159.342,50.991 ccw(c159.342,51.266) 159.617,51.266 ccw(c159.342,51.266) 159.342,51.541 ccw(c159.342,51.266) 159.067,51.266 ccw(c159.342,51.266)
cut-out: 160.104,48.663 ccw(c160.104,48.938) 160.379,48.938 ccw(c160.104,48.938) 160.104,49.213 ccw(c160.104,48.938) 159.829,48.938 ccw(c160.104,48.938)
cut-out: 160.866,50.991 cw(c160.866,51.266) 160.591,51.266 cw(c160.866,51.266) 160.866,51.541 cw(c160.866,51.266) 161.141,51.266 cw(c160.866,51.266)
cut-out: 160.104,50.991 ccw(c160.104,51.266) 160.379,51.266 ccw(c160.104,51.266) 160.104,51.541 ccw(c160.104,51.266) 159.829,51.266 ccw(c160.104,51.266)
cut-out: 161.628,50.991 ccw(c161.628,51.266) 161.903,51.266 ccw(c161.628,51.266) 161.628,51.541 ccw(c161.628,51.266) 161.353,51.266 ccw(c161.628,51.266)
cut-out: 161.628,48.663 ccw(c161.628,48.938) 161.903,48.938 ccw(c161.628,48.938) 161.628,49.213 ccw(c161.628,48.938) 161.353,48.938 ccw(c161.628,48.938)
cut-out: 160.866,48.663 ccw(c160.866,48.938) 161.141,48.938 ccw(c160.866,48.938) 160.866,49.213 ccw(c160.866,48.938) 160.591,48.938 ccw(c160.866,48.938)
cut-out: 162.39,48.663 ccw(c162.39,48.938) 162.665,48.938 ccw(c162.39,48.938) 162.39,49.213 ccw(c162.39,48.938) 162.115,48.938 ccw(c162.39,48.938)
cut-out: 163.152,48.663 ccw(c163.152,48.938) 163.427,48.938 ccw(c163.152,48.938) 163.152,49.213 ccw(c163.152,48.938) 162.877,48.938 ccw(c163.152,48.938)
cut-out: 163.914,48.663 ccw(c163.914,48.938) 164.189,48.938 ccw(c163.914,48.938) 163.914,49.213 ccw(c163.914,48.938) 163.639,48.938 ccw(c163.914,48.938)
cut-out: 164.676,48.663 ccw(c164.676,48.938) 164.951,48.938 ccw(c164.676,48.938) 164.676,49.213 ccw(c164.676,48.938) 164.401,48.938 ccw(c164.676,48.938)
cut-out: 164.676,50.991 ccw(c164.676,51.266) 164.951,51.266 ccw(c164.676,51.266) 164.676,51.541 ccw(c164.676,51.266) 164.401,51.266 ccw(c164.676,51.266)
cut-out: 163.914,50.991 ccw(c163.914,51.266) 164.189,51.266 ccw(c163.914,51.266) 163.914,51.541 ccw(c163.914,51.266) 163.639,51.266 ccw(c163.914,51.266)
cut-out: 163.152,50.991 ccw(c163.152,51.266) 163.427,51.266 ccw(c163.152,51.266) 163.152,51.541 ccw(c163.152,51.266) 162.877,51.266 ccw(c163.152,51.266)
cut-out: 162.39,50.991 ccw(c162.39,51.266) 162.665,51.266 ccw(c162.39,51.266) 162.39,51.541 ccw(c162.39,51.266) 162.115,51.266 ccw(c162.39,51.266)
cut-out: 144.06,48.663 ccw(c144.06,48.938) 144.335,48.938 ccw(c144.06,48.938) 144.06,49.213 ccw(c144.06,48.938) 143.785,48.938 ccw(c144.06,48.938)
cut-out: 144.06,50.991 ccw(c144.06,51.266) 144.335,51.266 ccw(c144.06,51.266) 144.06,51.541 ccw(c144.06,51.266) 143.785,51.266 ccw(c144.06,51.266)
cut-out: 144.822,48.663 ccw(c144.822,48.938) 145.097,48.938 ccw(c144.822,48.938) 144.822,49.213 ccw(c144.822,48.938) 144.547,48.938 ccw(c144.822,48.938)
cut-out: 145.584,50.991 cw(c145.584,51.266) 145.309,51.266 cw(c145.584,51.266) 145.584,51.541 cw(c145.584,51.266) 145.859,51.266 cw(c145.584,51.266)
cut-out: 144.822,50.991 ccw(c144.822,51.266) 145.097,51.266 ccw(c144.822,51.266) 144.822,51.541 ccw(c144.822,51.266) 144.547,51.266 ccw(c144.822,51.266)
cut-out: 146.346,50.991 ccw(c146.346,51.266) 146.621,51.266 ccw(c146.346,51.266) 146.346,51.541 ccw(c146.346,51.266) 146.071,51.266 ccw(c146.346,51.266)
cut-out: 146.346,48.663 ccw(c146.346,48.938) 146.621,48.938 ccw(c146.346,48.938) 146.346,49.213 ccw(c146.346,48.938) 146.071,48.938 ccw(c146.346,48.938)
cut-out: 145.584,48.663 ccw(c145.584,48.938) 145.859,48.938 ccw(c145.584,48.938) 145.584,49.213 ccw(c145.584,48.938) 145.309,48.938 ccw(c145.584,48.938)
cut-out: 147.108,48.663 ccw(c147.108,48.938) 147.383,48.938 ccw(c147.108,48.938) 147.108,49.213 ccw(c147.108,48.938) 146.833,48.938 ccw(c147.108,48.938)
cut-out: 147.87,48.663 ccw(c147.87,48.938) 148.145,48.938 ccw(c147.87,48.938) 147.87,49.213 ccw(c147.87,48.938) 147.595,48.938 ccw(c147.87,48.938)
cut-out: 148.632,48.663 ccw(c148.632,48.938) 148.907,48.938 ccw(c148.632,48.938) 148.632,49.213 ccw(c148.632,48.938) 148.357,48.938 ccw(c148.632,48.938)
cut-out: 149.394,48.663 ccw(c149.394,48.938) 149.669,48.938 ccw(c149.394,48.938) 149.394,49.213 ccw(c149.394,48.938) 149.119,48.938 ccw(c149.394,48.938)
cut-out: 149.394,50.991 ccw(c149.394,51.266) 149.669,51.266 ccw(c149.394,51.266) 149.394,51.541 ccw(c149.394,51.266) 149.119,51.266 ccw(c149.394,51.266)
cut-out: 148.632,50.991 ccw(c148.632,51.266) 148.907,51.266 ccw(c148.632,51.266) 148.632,51.541 ccw(c148.632,51.266) 148.357,51.266 ccw(c148.632,51.266)
cut-out: 147.87,50.991 ccw(c147.87,51.266) 148.145,51.266 ccw(c147.87,51.266) 147.87,51.541 ccw(c147.87,51.266) 147.595,51.266 ccw(c147.87,51.266)
cut-out: 147.108,50.991 ccw(c147.108,51.266) 147.383,51.266 ccw(c147.108,51.266) 147.108,51.541 ccw(c147.108,51.266) 146.833,51.266 ccw(c147.108,51.266)
cut-out: 128.778,48.663 ccw(c128.778,48.938) 129.053,48.938 ccw(c128.778,48.938) 128.778,49.213 ccw(c128.778,48.938) 128.503,48.938 ccw(c128.778,48.938)
cut-out: 128.778,50.991 ccw(c128.778,51.266) 129.053,51.266 ccw(c128.778,51.266) 128.778,51.541 ccw(c128.778,51.266) 128.503,51.266 ccw(c128.778,51.266)
cut-out: 129.54,48.663 ccw(c129.54,48.938) 129.815,48.938 ccw(c129.54,48.938) 129.54,49.213 ccw(c129.54,48.938) 129.265,48.938 ccw(c129.54,48.938)
cut-out: 130.302,50.991 cw(c130.302,51.266) 130.027,51.266 cw(c130.302,51.266) 130.302,51.541 cw(c130.302,51.266) 130.577,51.266 cw(c130.302,51.266)
cut-out: 129.54,50.991 ccw(c129.54,51.266) 129.815,51.266 ccw(c129.54,51.266) 129.54,51.541 ccw(c129.54,51.266) 129.265,51.266 ccw(c129.54,51.266)
cut-out: 131.064,50.991 ccw(c131.064,51.266) 131.339,51.266 ccw(c131.064,51.266) 131.064,51.541 ccw(c131.064,51.266) 130.789,51.266 ccw(c131.064,51.266)
cut-out: 131.064,48.663 ccw(c131.064,48.938) 131.339,48.938 ccw(c131.064,48.938) 131.064,49.213 ccw(c131.064,48.938) 130.789,48.938 ccw(c131.064,48.938)
cut-out: 130.302,48.663 ccw(c130.302,48.938) 130.577,48.938 ccw(c130.302,48.938) 130.302,49.213 ccw(c130.302,48.938) 130.027,48.938 ccw(c130.302,48.938)
cut-out: 131.826,48.663 ccw(c131.826,48.938) 132.101,48.938 ccw(c131.826,48.938) 131.826,49.213 ccw(c131.826,48.938) 131.551,48.938 ccw(c131.826,48.938)
cut-out: 132.588,48.663 ccw(c132.588,48.938) 132.863,48.938 ccw(c132.588,48.938) 132.588,49.213 ccw(c132.588,48.938) 132.313,48.938 ccw(c132.588,48.938)
cut-out: 133.35,48.663 ccw(c133.35,48.938) 133.625,48.938 ccw(c133.35,48.938) 133.35,49.213 ccw(c133.35,48.938) 133.075,48.938 ccw(c133.35,48.938)
cut-out: 134.112,48.663 ccw(c134.112,48.938) 134.387,48.938 ccw(c134.112,48.938) 134.112,49.213 ccw(c134.112,48.938) 133.837,48.938 ccw(c134.112,48.938)
cut-out: 134.112,50.991 ccw(c134.112,51.266) 134.387,51.266 ccw(c134.112,51.266) 134.112,51.541 ccw(c134.112,51.266) 133.837,51.266 ccw(c134.112,51.266)
cut-out: 133.35,50.991 ccw(c133.35,51.266) 133.625,51.266 ccw(c133.35,51.266) 133.35,51.541 ccw(c133.35,51.266) 133.075,51.266 ccw(c133.35,51.266)
cut-out: 132.588,50.991 ccw(c132.588,51.266) 132.863,51.266 ccw(c132.588,51.266) 132.588,51.541 ccw(c132.588,51.266) 132.313,51.266 ccw(c132.588,51.266)
cut-out: 131.826,50.991 ccw(c131.826,51.266) 132.101,51.266 ccw(c131.826,51.266) 131.826,51.541 ccw(c131.826,51.266) 131.551,51.266 ccw(c131.826,51.266)
cut-out: 205.188,71.565 ccw(c205.188,71.84) 205.463,71.84 ccw(c205.188,71.84) 205.188,72.115 ccw(c205.188,71.84) 204.913,71.84 ccw(c205.188,71.84)
cut-out: 205.188,73.893 ccw(c205.188,74.168) 205.463,74.168 ccw(c205.188,74.168) 205.188,74.443 ccw(c205.188,74.168) 204.913,74.168 ccw(c205.188,74.168)
cut-out: 205.95,71.565 ccw(c205.95,71.84) 206.225,71.84 ccw(c205.95,71.84) 205.95,72.115 ccw(c205.95,71.84) 205.675,71.84 ccw(c205.95,71.84)
cut-out: 206.712,73.893 cw(c206.712,74.168) 206.437,74.168 cw(c206.712,74.168) 206.712,74.443 cw(c206.712,74.168) 206.987,74.168 cw(c206.712,74.168)
cut-out: 205.95,73.893 ccw(c205.95,74.168) 206.225,74.168 ccw(c205.95,74.168) 205.95,74.443 ccw(c205.95,74.168) 205.675,74.168 ccw(c205.95,74.168)
cut-out: 207.474,73.893 ccw(c207.474,74.168) 207.749,74.168 ccw(c207.474,74.168) 207.474,74.443 ccw(c207.474,74.168) 207.199,74.168 ccw(c207.474,74.168)
cut-out: 207.474,71.565 ccw(c207.474,71.84) 207.749,71.84 ccw(c207.474,71.84) 207.474,72.115 ccw(c207.474,71.84) 207.199,71.84 ccw(c207.474,71.84)
cut-out: 206.712,71.565 ccw(c206.712,71.84) 206.987,71.84 ccw(c206.712,71.84) 206.712,72.115 ccw(c206.712,71.84) 206.437,71.84 ccw(c206.712,71.84)
cut-out: 208.236,71.565 ccw(c208.236,71.84) 208.511,71.84 ccw(c208.236,71.84) 208.236,72.115 ccw(c208.236,71.84) 207.961,71.84 ccw(c208.236,71.84)
cut-out: 208.998,71.565 ccw(c208.998,71.84) 209.273,71.84 ccw(c208.998,71.84) 208.998,72.115 ccw(c208.998,71.84) 208.723,71.84 ccw(c208.998,71.84)
cut-out: 209.76,71.565 ccw(c209.76,71.84) 210.035,71.84 ccw(c209.76,71.84) 209.76,72.115 ccw(c209.76,71.84) 209.485,71.84 ccw(c209.76,71.84)
cut-out: 210.522,71.565 ccw(c210.522,71.84) 210.797,71.84 ccw(c210.522,71.84) 210.522,72.115 ccw(c210.522,71.84) 210.247,71.84 ccw(c210.522,71.84)
cut-out: 210.522,73.893 ccw(c210.522,74.168) 210.797,74.168 ccw(c210.522,74.168) 210.522,74.443 ccw(c210.522,74.168) 210.247,74.168 ccw(c210.522,74.168)
cut-out: 209.76,73.893 ccw(c209.76,74.168) 210.035,74.168 ccw(c209.76,74.168) 209.76,74.443 ccw(c209.76,74.168) 209.485,74.168 ccw(c209.76,74.168)
cut-out: 208.998,73.893 ccw(c208.998,74.168) 209.273,74.168 ccw(c208.998,74.168) 208.998,74.443 ccw(c208.998,74.168) 208.723,74.168 ccw(c208.998,74.168)
cut-out: 208.236,73.893 ccw(c208.236,74.168) 208.511,74.168 ccw(c208.236,74.168) 208.236,74.443 ccw(c208.236,74.168) 207.961,74.168 ccw(c208.236,74.168)
cut-out: 189.906,71.565 ccw(c189.906,71.84) 190.181,71.84 ccw(c189.906,71.84) 189.906,72.115 ccw(c189.906,71.84) 189.631,71.84 ccw(c189.906,71.84)
cut-out: 189.906,73.893 ccw(c189.906,74.168) 190.181,74.168 ccw(c189.906,74.168) 189.906,74.443 ccw(c189.906,74.168) 189.631,74.168 ccw(c189.906,74.168)
cut-out: 190.668,71.565 ccw(c190.668,71.84) 190.943,71.84 ccw(c190.668,71.84) 190.668,72.115 ccw(c190.668,71.84) 190.393,71.84 ccw(c190.668,71.84)
cut-out: 191.43,73.893 cw(c191.43,74.168) 191.155,74.168 cw(c191.43,74.168) 191.43,74.443 cw(c191.43,74.168) 191.705,74.168 cw(c191.43,74.168)
cut-out: 190.668,73.893 ccw(c190.668,74.168) 190.943,74.168 ccw(c190.668,74.168) 190.668,74.443 ccw(c190.668,74.168) 190.393,74.168 ccw(c190.668,74.168)
cut-out: 192.192,73.893 ccw(c192.192,74.168) 192.467,74.168 ccw(c192.192,74.168) 192.192,74.443 ccw(c192.192,74.168) 191.917,74.168 ccw(c192.192,74.168)
cut-out: 192.192,71.565 ccw(c192.192,71.84) 192.467,71.84 ccw(c192.192,71.84) 192.192,72.115 ccw(c192.192,71.84) 191.917,71.84 ccw(c192.192,71.84)
cut-out: 191.43,71.565 ccw(c191.43,71.84) 191.705,71.84 ccw(c191.43,71.84) 191.43,72.115 ccw(c191.43,71.84) 191.155,71.84 ccw(c191.43,71.84)
cut-out: 192.954,71.565 ccw(c192.954,71.84) 193.229,71.84 ccw(c192.954,71.84) 192.954,72.115 ccw(c192.954,71.84) 192.679,71.84 ccw(c192.954,71.84)
cut-out: 193.716,71.565 ccw(c193.716,71.84) 193.991,71.84 ccw(c193.716,71.84) 193.716,72.115 ccw(c193.716,71.84) 193.441,71.84 ccw(c193.716,71.84)
cut-out: 194.478,71.565 ccw(c194.478,71.84) 194.753,71.84 ccw(c194.478,71.84) 194.478,72.115 ccw(c194.478,71.84) 194.203,71.84 ccw(c194.478,71.84)
cut-out: 195.24,71.565 ccw(c195.24,71.84) 195.515,71.84 ccw(c195.24,71.84) 195.24,72.115 ccw(c195.24,71.84) 194.965,71.84 ccw(c195.24,71.84)
cut-out: 195.24,73.893 ccw(c195.24,74.168) 195.515,74.168 ccw(c195.24,74.168) 195.24,74.443 ccw(c195.24,74.168) 194.965,74.168 ccw(c195.24,74.168)
cut-out: 194.478,73.893 ccw(c194.478,74.168) 194.753,74.168 ccw(c194.478,74.168) 194.478,74.443 ccw(c194.478,74.168) 194.203,74.168 ccw(c194.478,74.168)
cut-out: 193.716,73.893 ccw(c193.716,74.168) 193.991,74.168 ccw(c193.716,74.168) 193.716,74.443 ccw(c193.716,74.168) 193.441,74.168 ccw(c193.716,74.168)
cut-out: 192.954,73.893 ccw(c192.954,74.168) 193.229,74.168 ccw(c192.954,74.168) 192.954,74.443 ccw(c192.954,74.168) 192.679,74.168 ccw(c192.954,74.168)
cut-out: 174.624,71.565 ccw(c174.624,71.84) 174.899,71.84 ccw(c174.624,71.84) 174.624,72.115 ccw(c174.624,71.84) 174.349,71.84 ccw(c174.624,71.84)
cut-out: 174.624,73.893 ccw(c174.624,74.168) 174.899,74.168 ccw(c174.624,74.168) 174.624,74.443 ccw(c174.624,74.168) 174.349,74.168 ccw(c174.624,74.168)
cut-out: 175.386,71.565 ccw(c175.386,71.84) 175.661,71.84 ccw(c175.386,71.84) 175.386,72.115 ccw(c175.386,71.84) 175.111,71.84 ccw(c175.386,71.84)
cut-out: 176.148,73.893 cw(c176.148,74.168) 175.873,74.168 cw(c176.148,74.168) 176.148,74.443 cw(c176.148,74.168) 176.423,74.168 cw(c176.148,74.168)
cut-out: 175.386,73.893 ccw(c175.386,74.168) 175.661,74.168 ccw(c175.386,74.168) 175.386,74.443 ccw(c175.386,74.168) 175.111,74.168 ccw(c175.386,74.168)
cut-out: 176.91,73.893 ccw(c176.91,74.168) 177.185,74.168 ccw(c176.91,74.168) 176.91,74.443 ccw(c176.91,74.168) 176.635,74.168 ccw(c176.91,74.168)
cut-out: 176.91,71.565 ccw(c176.91,71.84) 177.185,71.84 ccw(c176.91,71.84) 176.91,72.115 ccw(c176.91,71.84) 176.635,71.84 ccw(c176.91,71.84)
cut-out: 176.148,71.565 ccw(c176.148,71.84) 176.423,71.84 ccw(c176.148,71.84) 176.148,72.115 ccw(c176.148,71.84) 175.873,71.84 ccw(c176.148,71.84)
cut-out: 177.672,71.565 ccw(c177.672,71.84) 177.947,71.84 ccw(c177.672,71.84) 177.672,72.115 ccw(c177.672,71.84) 177.397,71.84 ccw(c177.672,71.84)
cut-out: 178.434,71.565 ccw(c178.434,71.84) 178.709,71.84 ccw(c178.434,71.84) 178.434,72.115 ccw(c178.434,71.84) 178.159,71.84 ccw(c178.434,71.84)
cut-out: 179.196,71.565 ccw(c179.196,71.84) 179.471,71.84 ccw(c179.196,71.84) 179.196,72.115 ccw(c179.196,71.84) 178.921,71.84 ccw(c179.196,71.84)
cut-out: 179.958,71.565 ccw(c179.958,71.84) 180.233,71.84 ccw(c179.958,71.84) 179.958,72.115 ccw(c179.958,71.84) 179.683,71.84 ccw(c179.958,71.84)
cut-out: 179.958,73.893 ccw(c179.958,74.168) 180.233,74.168 ccw(c179.958,74.168) 179.958,74.443 ccw(c179.958,74.168) 179.683,74.168 ccw(c179.958,74.168)
cut-out: 179.196,73.893 ccw(c179.196,74.168) 179.471,74.168 ccw(c179.196,74.168) 179.196,74.443 ccw(c179.196,74.168) 178.921,74.168 ccw(c179.196,74.168)
cut-out: 178.434,73.893 ccw(c178.434,74.168) 178.709,74.168 ccw(c178.434,74.168) 178.434,74.443 ccw(c178.434,74.168) 178.159,74.168 ccw(c178.434,74.168)
cut-out: 177.672,73.893 ccw(c177.672,74.168) 177.947,74.168 ccw(c177.672,74.168) 177.672,74.443 ccw(c177.672,74.168) 177.397,74.168 ccw(c177.672,74.168)
cut-out: 159.342,71.565 ccw(c159.342,71.84) 159.617,71.84 ccw(c159.342,71.84) 159.342,72.115 ccw(c159.342,71.84) 159.067,71.84 ccw(c159.342,71.84)
cut-out: 159.342,73.893 ccw(c159.342,74.168) 159.617,74.168 ccw(c159.342,74.168) 159.342,74.443 ccw(c159.342,74.168) 159.067,74.168 ccw(c159.342,74.168)
cut-out: 160.104,71.565 ccw(c160.104,71.84) 160.379,71.84 ccw(c160.104,71.84) 160.104,72.115 ccw(c160.104,71.84) 159.829,71.84 ccw(c160.104,71.84)
cut-out: 160.866,73.893 cw(c160.866,74.168) 160.591,74.168 cw(c160.866,74.168) 160.866,74.443 cw(c160.866,74.168) 161.141,74.168 cw(c160.866,74.168)
cut-out: 160.104,73.893 ccw(c160.104,74.168) 160.379,74.168 ccw(c160.104,74.168) 160.104,74.443 ccw(c160.104,74.168) 159.829,74.168 ccw(c160.104,74.168)
cut-out: 161.628,73.893 ccw(c161.628,74.168) 161.903,74.168 ccw(c161.628,74.168) 161.628,74.443 ccw(c161.628,74.168) 161.353,74.168 ccw(c161.628,74.168)
cut-out: 161.628,71.565 ccw(c161.628,71.84) 161.903,71.84 ccw(c161.628,71.84) 161.628,72.115 ccw(c161.628,71.84) 161.353,71.84 ccw(c161.628,71.84)
cut-out: 160.866,71.565 ccw(c160.866,71.84) 161.141,71.84 ccw(c160.866,71.84) 160.866,72.115 ccw(c160.866,71.84) 160.591,71.84 ccw(c160.866,71.84)
cut-out: 162.39,71.565 ccw(c162.39,71.84) 162.665,71.84 ccw(c162.39,71.84) 162.39,72.115 ccw(c162.39,71.84) 162.115,71.84 ccw(c162.39,71.84)
cut-out: 163.152,71.565 ccw(c163.152,71.84) 163.427,71.84 ccw(c163.152,71.84) 163.152,72.115 ccw(c163.152,71.84) 162.877,71.84 ccw(c163.152,71.84)
cut-out: 163.914,71.565 ccw(c163.914,71.84) 164.189,71.84 ccw(c163.914,71.84) 163.914,72.115 ccw(c163.914,71.84) 163.639,71.84 ccw(c163.914,71.84)
cut-out: 164.676,71.565 ccw(c164.676,71.84) 164.951,71.84 ccw(c164.676,71.84) 164.676,72.115 ccw(c164.676,71.84) 164.401,71.84 ccw(c164.676,71.84)
cut-out: 164.676,73.893 ccw(c164.676,74.168) 164.951,74.168 ccw(c164.676,74.168) 164.676,74.443 ccw(c164.676,74.168) 164.401,74.168 ccw(c164.676,74.168)
cut-out: 163.914,73.893 ccw(c163.914,74.168) 164.189,74.168 ccw(c163.914,74.168) 163.914,74.443 ccw(c163.914,74.168) 163.639,74.168 ccw(c163.914,74.168)
cut-out: 163.152,73.893 ccw(c163.152,74.168) 163.427,74.168 ccw(c163.152,74.168) 163.152,74.443 ccw(c163.152,74.168) 162.877,74.168 ccw(c163.152,74.168)
cut-out: 162.39,73.893 ccw(c162.39,74.168) 162.665,74.168 ccw(c162.39,74.168) 162.39,74.443 ccw(c162.39,74.168) 162.115,74.168 ccw(c162.39,74.168)
cut-out: 144.06,71.565 ccw(c144.06,71.84) 144.335,71.84 ccw(c144.06,71.84) 144.06,72.115 ccw(c144.06,71.84) 143.785,71.84 ccw(c144.06,71.84)
cut-out: 144.06,73.893 ccw(c144.06,74.168) 144.335,74.168 ccw(c144.06,74.168) 144.06,74.443 ccw(c144.06,74.168) 143.785,74.168 ccw(c144.06,74.168)
cut-out: 144.822,71.565 ccw(c144.822,71.84) 145.097,71.84 ccw(c144.822,71.84) 144.822,72.115 ccw(c144.822,71.84) 144.547,71.84 ccw(c144.822,71.84)
cut-out: 145.584,73.893 cw(c145.584,74.168) 145.309,74.168 cw(c145.584,74.168) 145.584,74.443 cw(c145.584,74.168) 145.859,74.168 cw(c145.584,74.168)
cut-out: 144.822,73.893 ccw(c144.822,74.168) 145.097,74.168 ccw(c144.822,74.168) 144.822,74.443 ccw(c144.822,74.168) 144.547,74.168 ccw(c144.822,74.168)
cut-out: 146.346,73.893 ccw(c146.346,74.168) 146.621,74.168 ccw(c146.346,74.168) 146.346,74.443 ccw(c146.346,74.168) 146.071,74.168 ccw(c146.346,74.168)
cut-out: 146.346,71.565 ccw(c146.346,71.84) 146.621,71.84 ccw(c146.346,71.84) 146.346,72.115 ccw(c146.346,71.84) 146.071,71.84 ccw(c146.346,71.84)
cut-out: 145.584,71.565 ccw(c145.584,71.84) 145.859,71.84 ccw(c145.584,71.84) 145.584,72.115 ccw(c145.584,71.84) 145.309,71.84 ccw(c145.584,71.84)
cut-out: 147.108,71.565 ccw(c147.108,71.84) 147.383,71.84 ccw(c147.108,71.84) 147.108,72.115 ccw(c147.108,71.84) 146.833,71.84 ccw(c147.108,71.84)
cut-out: 147.87,71.565 ccw(c147.87,71.84) 148.145,71.84 ccw(c147.87,71.84) 147.87,72.115 ccw(c147.87,71.84) 147.595,71.84 ccw(c147.87,71.84)
cut-out: 148.632,71.565 ccw(c148.632,71.84) 148.907,71.84 ccw(c148.632,71.84) 148.632,72.115 ccw(c148.632,71.84) 148.357,71.84 ccw(c148.632,71.84)
cut-out: 149.394,71.565 ccw(c149.394,71.84) 149.669,71.84 ccw(c149.394,71.84) 149.394,72.115 ccw(c149.394,71.84) 149.119,71.84 ccw(c149.394,71.84)
cut-out: 149.394,73.893 ccw(c149.394,74.168) 149.669,74.168 ccw(c149.394,74.168) 149.394,74.443 ccw(c149.394,74.168) 149.119,74.168 ccw(c149.394,74.168)
cut-out: 148.632,73.893 ccw(c148.632,74.168) 148.907,74.168 ccw(c148.632,74.168) 148.632,74.443 ccw(c148.632,74.168) 148.357,74.168 ccw(c148.632,74.168)
cut-out: 147.87,73.893 ccw(c147.87,74.168) 148.145,74.168 ccw(c147.87,74.168) 147.87,74.443 ccw(c147.87,74.168) 147.595,74.168 ccw(c147.87,74.168)
cut-out: 147.108,73.893 ccw(c147.108,74.168) 147.383,74.168 ccw(c147.108,74.168) 147.108,74.443 ccw(c147.108,74.168) 146.833,74.168 ccw(c147.108,74.168)
cut-out: 128.778,71.565 ccw(c128.778,71.84) 129.053,71.84 ccw(c128.778,71.84) 128.778,72.115 ccw(c128.778,71.84) 128.503,71.84 ccw(c128.778,71.84)
cut-out: 128.778,73.893 ccw(c128.778,74.168) 129.053,74.168 ccw(c128.778,74.168) 128.778,74.443 ccw(c128.778,74.168) 128.503,74.168 ccw(c128.778,74.168)
cut-out: 129.54,71.565 ccw(c129.54,71.84) 129.815,71.84 ccw(c129.54,71.84) 129.54,72.115 ccw(c129.54,71.84) 129.265,71.84 ccw(c129.54,71.84)
cut-out: 130.302,73.893 cw(c130.302,74.168) 130.027,74.168 cw(c130.302,74.168) 130.302,74.443 cw(c130.302,74.168) 130.577,74.168 cw(c130.302,74.168)
cut-out: 129.54,73.893 ccw(c129.54,74.168) 129.815,74.168 ccw(c129.54,74.168) 129.54,74.443 ccw(c129.54,74.168) 129.265,74.168 ccw(c129.54,74.168)
cut-out: 131.064,73.893 ccw(c131.064,74.168) 131.339,74.168 ccw(c131.064,74.168) 131.064,74.443 ccw(c131.064,74.168) 130.789,74.168 ccw(c131.064,74.168)
cut-out: 131.064,71.565 ccw(c131.064,71.84) 131.339,71.84 ccw(c131.064,71.84) 131.064,72.115 ccw(c131.064,71.84) 130.789,71.84 ccw(c131.064,71.84)
cut-out: 130.302,71.565 ccw(c130.302,71.84) 130.577,71.84 ccw(c130.302,71.84) 130.302,72.115 ccw(c130.302,71.84) 130.027,71.84 ccw(c130.302,71.84)
cut-out: 131.826,71.565 ccw(c131.826,71.84) 132.101,71.84 ccw(c131.826,71.84) 131.826,72.115 ccw(c131.826,71.84) 131.551,71.84 ccw(c131.826,71.84)
cut-out: 132.588,71.565 ccw(c132.588,71.84) 132.863,71.84 ccw(c132.588,71.84) 132.588,72.115 ccw(c132.588,71.84) 132.313,71.84 ccw(c132.588,71.84)
cut-out: 133.35,71.565 ccw(c133.35,71.84) 133.625,71.84 ccw(c133.35,71.84) 133.35,72.115 ccw(c133.35,71.84) 133.075,71.84 ccw(c133.35,71.84)
cut-out: 134.112,71.565 ccw(c134.112,71.84) 134.387,71.84 ccw(c134.112,71.84) 134.112,72.115 ccw(c134.112,71.84) 133.837,71.84 ccw(c134.112,71.84)
cut-out: 134.112,73.893 ccw(c134.112,74.168) 134.387,74.168 ccw(c134.112,74.168) 134.112,74.443 ccw(c134.112,74.168) 133.837,74.168 ccw(c134.112,74.168)
cut-out: 133.35,73.893 ccw(c133.35,74.168) 133.625,74.168 ccw(c133.35,74.168) 133.35,74.443 ccw(c133.35,74.168) 133.075,74.168 ccw(c133.35,74.168)
cut-out: 132.588,73.893 ccw(c132.588,74.168) 132.863,74.168 ccw(c132.588,74.168) 132.588,74.443 ccw(c132.588,74.168) 132.313,74.168 ccw(c132.588,74.168)
cut-out: 131.826,73.893 ccw(c131.826,74.168) 132.101,74.168 ccw(c131.826,74.168) 131.826,74.443 ccw(c131.826,74.168) 131.551,74.168 ccw(c131.826,74.168)
cut-out: 198.775,18.416 ccw(c199.05,18.416) 199.05,18.141 ccw(c199.05,18.416) 199.325,18.416 ccw(c199.05,18.416) 199.05,18.691 ccw(c199.05,18.416)
cut-out: 201.103,18.416 ccw(c201.378,18.416) 201.378,18.141 ccw(c201.378,18.416) 201.653,18.416 ccw(c201.378,18.416) 201.378,18.691 ccw(c201.378,18.416)
cut-out: 198.775,17.654 ccw(c199.05,17.654) 199.05,17.379 ccw(c199.05,17.654) 199.325,17.654 ccw(c199.05,17.654) 199.05,17.929 ccw(c199.05,17.654)
cut-out: 201.103,16.892 cw(c201.378,16.892) 201.378,17.167 cw(c201.378,16.892) 201.653,16.892 cw(c201.378,16.892) 201.378,16.617 cw(c201.378,16.892)
cut-out: 201.103,17.654 ccw(c201.378,17.654) 201.378,17.379 ccw(c201.378,17.654) 201.653,17.654 ccw(c201.378,17.654) 201.378,17.929 ccw(c201.378,17.654)
cut-out: 201.103,16.13 ccw(c201.378,16.13) 201.378,15.855 ccw(c201.378,16.13) 201.653,16.13 ccw(c201.378,16.13) 201.378,16.405 ccw(c201.378,16.13)
cut-out: 198.775,16.13 ccw(c199.05,16.13) 199.05,15.855 ccw(c199.05,16.13) 199.325,16.13 ccw(c199.05,16.13) 199.05,16.405 ccw(c199.05,16.13)
cut-out: 198.775,16.892 ccw(c199.05,16.892) 199.05,16.617 ccw(c199.05,16.892) 199.325,16.892 ccw(c199.05,16.892) 199.05,17.167 ccw(c199.05,16.892)
cut-out: 198.775,15.368 ccw(c199.05,15.368) 199.05,15.093 ccw(c199.05,15.368) 199.325,15.368 ccw(c199.05,15.368) 199.05,15.643 ccw(c199.05,15.368)
cut-out: 198.775,14.606 ccw(c199.05,14.606) 199.05,14.331 ccw(c199.05,14.606) 199.325,14.606 ccw(c199.05,14.606) 199.05,14.881 ccw(c199.05,14.606)
cut-out: 198.775,13.844 ccw(c199.05,13.844) 199.05,13.569 ccw(c199.05,13.844) 199.325,13.844 ccw(c199.05,13.844) 199.05,14.119 ccw(c199.05,13.844)
cut-out: 198.775,13.082 ccw(c199.05,13.082) 199.05,12.807 ccw(c199.05,13.082) 199.325,13.082 ccw(c199.05,13.082) 199.05,13.357 ccw(c199.05,13.082)
cut-out: 201.103,13.082 ccw(c201.378,13.082) 201.378,12.807 ccw(c201.378,13.082) 201.653,13.082 ccw(c201.378,13.082) 201.378,13.357 ccw(c201.378,13.082)
cut-out: 201.103,13.844 ccw(c201.378,13.844) 201.378,13.569 ccw(c201.378,13.844) 201.653,13.844 ccw(c201.378,13.844) 201.378,14.119 ccw(c201.378,13.844)
cut-out: 201.103,14.606 ccw(c201.378,14.606) 201.378,14.331 ccw(c201.378,14.606) 201.653,14.606 ccw(c201.378,14.606) 201.378,14.881 ccw(c201.378,14.606)
cut-out: 201.103,15.368 ccw(c201.378,15.368) 201.378,15.093 ccw(c201.378,15.368) 201.653,15.368 ccw(c201.378,15.368) 201.378,15.643 ccw(c201.378,15.368)
cut-out: 183.493,18.416 ccw(c183.768,18.416) 183.768,18.141 ccw(c183.768,18.416) 184.043,18.416 ccw(c183.768,18.416) 183.768,18.691 ccw(c183.768,18.416)
cut-out: 185.821,18.416 ccw(c186.096,18.416) 186.096,18.141 ccw(c186.096,18.416) 186.371,18.416 ccw(c186.096,18.416) 186.096,18.691 ccw(c186.096,18.416)
cut-out: 183.493,17.654 ccw(c183.768,17.654) 183.768,17.379 ccw(c183.768,17.654) 184.043,17.654 ccw(c183.768,17.654) 183.768,17.929 ccw(c183.768,17.654)
cut-out: 185.821,16.892 cw(c186.096,16.892) 186.096,17.167 cw(c186.096,16.892) 186.371,16.892 cw(c186.096,16.892) 186.096,16.617 cw(c186.096,16.892)
cut-out: 185.821,17.654 ccw(c186.096,17.654) 186.096,17.379 ccw(c186.096,17.654) 186.371,17.654 ccw(c186.096,17.654) 186.096,17.929 ccw(c186.096,17.654)
cut-out: 185.821,16.13 ccw(c186.096,16.13) 186.096,15.855 ccw(c186.096,16.13) 186.371,16.13 ccw(c186.096,16.13) 186.096,16.405 ccw(c186.096,16.13)
cut-out: 183.493,16.13 ccw(c183.768,16.13) 183.768,15.855 ccw(c183.768,16.13) 184.043,16.13 ccw(c183.768,16.13) 183.768,16.405 ccw(c183.768,16.13)
cut-out: 183.493,16.892 ccw(c183.768,16.892) 183.768,16.617 ccw(c183.768,16.892) 184.043,16.892 ccw(c183.768,16.892) 183.768,17.167 ccw(c183.768,16.892)
cut-out: 183.493,15.368 ccw(c183.768,15.368) 183.768,15.093 ccw(c183.768,15.368) 184.043,15.368 ccw(c183.768,15.368) 183.768,15.643 ccw(c183.768,15.368)
cut-out: 183.493,14.606 ccw(c183.768,14.606) 183.768,14.331 ccw(c183.768,14.606) 184.043,14.606 ccw(c183.768,14.606) 183.768,14.881 ccw(c183.768,14.606)
cut-out: 183.493,13.844 ccw(c183.768,13.844) 183.768,13.569 ccw(c183.768,13.844) 184.043,13.844 ccw(c183.768,13.844) 183.768,14.119 ccw(c183.768,13.844)
cut-out: 183.493,13.082 ccw(c183.768,13.082) 183.768,12.807 ccw(c183.768,13.082) 184.043,13.082 ccw(c183.768,13.082) 183.768,13.357 ccw(c183.768,13.082)
cut-out: 185.821,13.082 ccw(c186.096,13.082) 186.096,12.807 ccw(c186.096,13.082) 186.371,13.082 ccw(c186.096,13.082) 186.096,13.357 ccw(c186.096,13.082)
cut-out: 185.821,13.844 ccw(c186.096,13.844) 186.096,13.569 ccw(c186.096,13.844) 186.371,13.844 ccw(c186.096,13.844) 186.096,14.119 ccw(c186.096,13.844)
